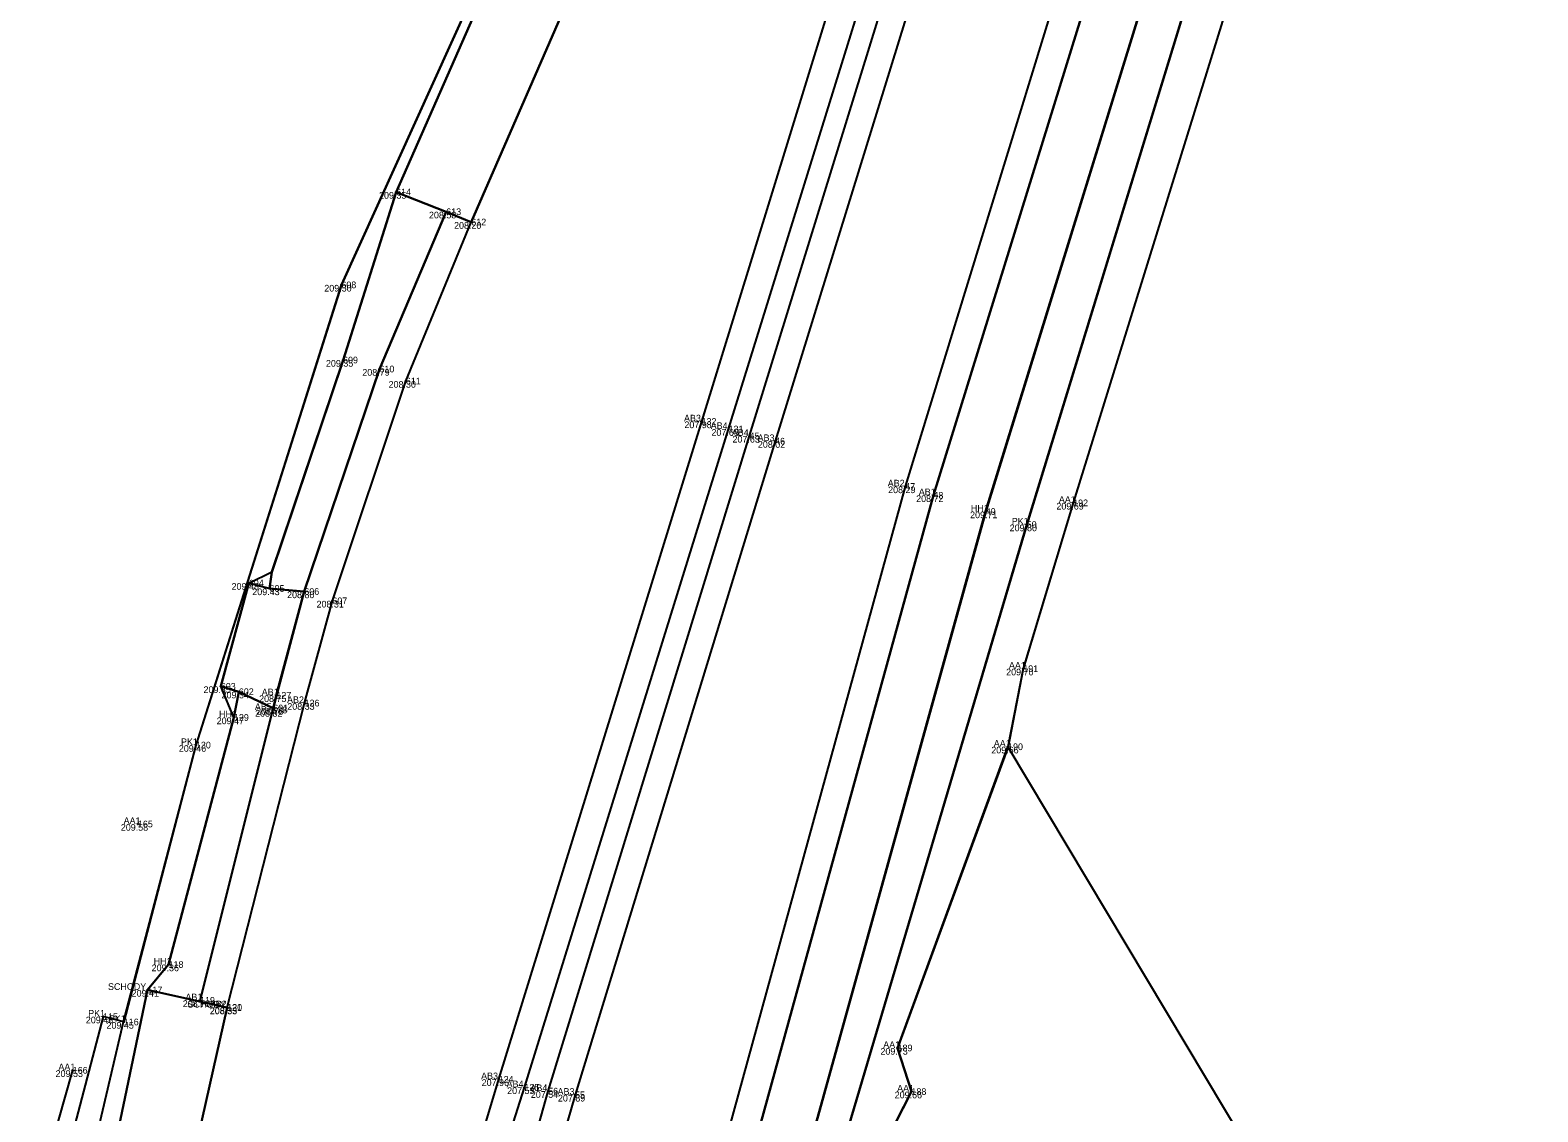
# Model space of a CAD drawing. Extents: x -262982 to -262706, y -1238714 to -1237093.
# Drawn here: x -262956 to -262910.85, y -1238361.66 to -1238329.27 of the extents above; entities that cross this region are included whole.
import ezdxf

# ---------------------------------------------------------------- set-up
doc = ezdxf.new("R2010")
doc.units = 0
for name, color, linetype in [('01_Hrana_betónu', 7, 'Continuous'), ('02_Oplotenie', 7, 'Continuous'), ('03_Asfalt', 7, 'Continuous'), ('05_Hrana_terénu', 7, 'Continuous'), ('06_Schody', 7, 'Continuous'), ('07_Iné', 7, 'Continuous'), ('Groma (21)', 7, 'Continuous'), ('Groma (22)', 7, 'Continuous'), ('Groma (23)', 7, 'Continuous'), ('Groma (24)', 7, 'Continuous'), ('U002_Asfalt', 7, 'Continuous'), ('U002_Betónové panely', 7, 'Continuous'), ('U002_Betóny_prídavné', 7, 'Continuous'), ('U002_Schody', 7, 'Continuous'), ('U002_Zeleň_mimo', 7, 'Continuous'), ('U002_Zeleň_vnútro', 7, 'Continuous'), ('U002_Zeleň_zatrávňovač', 7, 'Continuous')]:
    doc.layers.add(name, color=color, linetype=linetype)

msp = doc.modelspace()

# ---------------------------------------------------------------- linework, layer by layer
at = {"layer": '01_Hrana_betónu'}
for points in [[(-262944.213, -1238387.387), (-262944.634, -1238381.789), (-262944.5, -1238371.343), (-262941.2, -1238360.927), (-262935.086, -1238341.218), (-262927.632, -1238317.179), (-262920.793, -1238295.265), (-262911.171, -1238262.813), (-262915.352, -1238261.064), (-262915.337, -1238259.329), (-262909.866, -1238261.629), (-262904.904, -1238263.716)], [(-262916.095, -1238261.519), (-262911.974, -1238263.293), (-262921.591, -1238294.909), (-262928.534, -1238317.073), (-262935.896, -1238340.99), (-262941.971, -1238360.685), (-262945.096, -1238371.115), (-262945.34, -1238381.803), (-262945.412, -1238387.557)], [(-262941.714, -1238387.032), (-262942.991, -1238380.859), (-262943.934, -1238373.35), (-262940.485, -1238361.041), (-262934.456, -1238341.421), (-262927.277, -1238318.134), (-262920.116, -1238294.802), (-262913.64, -1238273.614), (-262910.214, -1238263.245), (-262905.769, -1238265.099), (-262904.904, -1238263.716)], [(-262905.769, -1238265.099), (-262909.81, -1238264.181), (-262912.956, -1238273.861), (-262919.396, -1238295.066), (-262926.538, -1238318.409), (-262933.693, -1238341.579), (-262939.683, -1238361.151), (-262943.246, -1238373.477), (-262942.259, -1238380.752), (-262940.526, -1238386.713)], [(-262905.769, -1238265.099), (-262909.014, -1238275.12), (-262915.393, -1238296.189), (-262922.597, -1238319.497), (-262929.796, -1238342.936), (-262935.083, -1238362.17), (-262937.995, -1238374.567), (-262938.788, -1238380.26), (-262939.46, -1238386.668), (-262940.526, -1238386.713), (-262940.498, -1238386.859)], [(-262940.36, -1238387.407), (-262939.388, -1238387.391), (-262938.822, -1238386.902), (-262937.88, -1238380.385), (-262937.119, -1238374.802), (-262934.23, -1238362.39), (-262928.952, -1238343.2), (-262921.717, -1238319.813), (-262915.107, -1238298.192), (-262908.208, -1238275.423), (-262904.855, -1238265.436)], [(-262950.921, -1238358.358), (-262948.72, -1238349.57), (-262948.626, -1238349.19), (-262947.79, -1238346.08), (-262945.54, -1238339.42), (-262943.54, -1238334.71)], [(-262950.104, -1238358.539), (-262947.782, -1238349.422), (-262946.95, -1238346.36), (-262944.75, -1238339.78), (-262942.79, -1238335.02)]]:
    msp.add_lwpolyline(points, dxfattribs=at)
at = {"layer": '02_Oplotenie'}
msp.add_lwpolyline([(-262939.39, -1238320.83), (-262941.19, -1238324.79), (-262946.68, -1238336.9), (-262951.035, -1238350.68), (-262953.195, -1238358.97), (-262953.815, -1238358.809), (-262955.312, -1238364.513), (-262954.553, -1238364.724), (-262954.681, -1238366.785), (-262954.024, -1238372.698), (-262953.142, -1238376.2), (-262951.104, -1238384.342), (-262949.016, -1238390.045), (-262944.443, -1238389.969), (-262936.906, -1238389.616), (-262935.581, -1238380.82), (-262934.566, -1238375.513), (-262931.812, -1238363.194), (-262926.159, -1238344.076), (-262918.903, -1238320.384), (-262912.242, -1238298.942), (-262905.326, -1238276.054), (-262902.598, -1238266.292), (-262902.107, -1238264.892)], dxfattribs=at)
at = {"layer": '03_Asfalt'}
for points in [[(-262917.941, -1238321.4), (-262924.768, -1238343.427), (-262926.262, -1238348.392), (-262926.717, -1238350.729), (-262930.026, -1238359.749), (-262929.61, -1238361.054), (-262931.199, -1238364.162)], [(-262955.999, -1238364.917), (-262954.725, -1238360.416)]]:
    msp.add_lwpolyline(points, dxfattribs=at)
at = {"layer": '05_Hrana_terénu'}
msp.add_lwpolyline([(-262920.126, -1238320.151), (-262927.385, -1238343.686), (-262932.704, -1238362.854), (-262935.453, -1238375.219), (-262936.279, -1238380.57), (-262937.519, -1238387.253), (-262938.314, -1238388.733), (-262939.759, -1238389.403), (-262945.681, -1238389.45), (-262947.587, -1238388.865), (-262949.049, -1238387.288), (-262950.436, -1238384.21), (-262953.347, -1238372.702), (-262953.777, -1238366.63), (-262954.163, -1238366.041), (-262952.487, -1238358.01), (-262951.855, -1238357.25), (-262949.897, -1238349.853), (-262950.29, -1238348.92), (-262949.45, -1238345.83), (-262948.76, -1238345.496), (-262946.63, -1238339.15), (-262945.04, -1238334.12), (-262941.75, -1238326.63)], dxfattribs=at)
at = {"layer": '06_Schody'}
for points in [[(-262942.79, -1238335.02), (-262943.54, -1238334.71), (-262945.04, -1238334.12), (-262941.75, -1238326.63), (-262940.4, -1238327.16), (-262939.53, -1238327.53)], [(-262951.91, -1238366.581), (-262952.759, -1238366.382), (-262954.163, -1238366.041), (-262952.487, -1238358.01), (-262950.921, -1238358.358), (-262950.104, -1238358.539)]]:
    msp.add_lwpolyline(points, close=True, dxfattribs=at)
at = {"layer": '07_Iné'}
msp.add_lwpolyline([(-262948.72, -1238349.57), (-262949.75, -1238349.08), (-262950.29, -1238348.92), (-262949.45, -1238345.83), (-262948.83, -1238345.99), (-262947.79, -1238346.08)], dxfattribs=at)
at = {"layer": 'Groma (21)'}
for centre in [(-262945.04, -1238334.12), (-262943.54, -1238334.71), (-262942.79, -1238335.02), (-262946.68, -1238336.9), (-262946.63, -1238339.15), (-262945.54, -1238339.42), (-262944.75, -1238339.78), (-262935.896, -1238340.99), (-262935.086, -1238341.218), (-262934.456, -1238341.421), (-262933.693, -1238341.579), (-262929.796, -1238342.936), (-262928.952, -1238343.2), (-262924.768, -1238343.427), (-262927.385, -1238343.686), (-262926.159, -1238344.076), (-262949.45, -1238345.83), (-262948.83, -1238345.99), (-262947.79, -1238346.08), (-262946.95, -1238346.36), (-262926.262, -1238348.392), (-262950.29, -1238348.92), (-262949.75, -1238349.08), (-262948.626, -1238349.19), (-262948.747, -1238349.629), (-262948.72, -1238349.57), (-262947.782, -1238349.422), (-262949.897, -1238349.853), (-262951.035, -1238350.68), (-262926.717, -1238350.729), (-262952.772, -1238353.044), (-262951.855, -1238357.25), (-262952.487, -1238358.01), (-262950.912, -1238358.322), (-262953.815, -1238358.809), (-262950.104, -1238358.539), (-262950.099, -1238358.531), (-262953.195, -1238358.97), (-262930.026, -1238359.749), (-262954.725, -1238360.416), (-262941.971, -1238360.685), (-262941.2, -1238360.927), (-262940.485, -1238361.041), (-262929.61, -1238361.054), (-262939.683, -1238361.151)]:
    msp.add_circle(centre, 0.01, dxfattribs=at)
at = {"layer": 'U002_Asfalt'}
msp.add_lwpolyline([(-262931.2, -1238364.16), (-262929.61, -1238361.05), (-262930.03, -1238359.75), (-262926.72, -1238350.73), (-262915.49, -1238369.52)], dxfattribs=at)
at = {"layer": 'U002_Betónové panely'}
for points in [[(-262921.72, -1238319.81), (-262928.95, -1238343.2), (-262934.23, -1238362.39)], [(-262951.91, -1238366.58), (-262950.1, -1238358.54), (-262950.92, -1238358.36), (-262948.72, -1238349.57), (-262948.63, -1238349.19), (-262947.79, -1238346.08), (-262945.54, -1238339.42), (-262943.54, -1238334.71), (-262942.79, -1238335.02), (-262939.53, -1238327.53)]]:
    msp.add_lwpolyline(points, dxfattribs=at)
at = {"layer": 'U002_Betóny_prídavné'}
msp.add_lwpolyline([(-262948.72, -1238349.57), (-262949.75, -1238349.08), (-262950.29, -1238348.92), (-262949.45, -1238345.83), (-262948.83, -1238345.99), (-262947.79, -1238346.08)], close=True, dxfattribs=at)
at = {"layer": 'U002_Schody'}
for points in [[(-262943.54, -1238334.71), (-262945.04, -1238334.12), (-262941.75, -1238326.63), (-262940.4, -1238327.16), (-262939.53, -1238327.53), (-262942.79, -1238335.02)], [(-262950.1, -1238358.54), (-262951.91, -1238366.58), (-262952.76, -1238366.38), (-262954.16, -1238366.04), (-262952.49, -1238358.01), (-262950.92, -1238358.36)]]:
    msp.add_lwpolyline(points, close=True, dxfattribs=at)
at = {"layer": 'U002_Zeleň_mimo'}
for points in [[(-262931.81, -1238363.19), (-262926.16, -1238344.08), (-262918.9, -1238320.38)], [(-262917.94, -1238321.4), (-262924.77, -1238343.43), (-262926.26, -1238348.39), (-262926.72, -1238350.73), (-262930.03, -1238359.75), (-262929.61, -1238361.05), (-262931.2, -1238364.16)]]:
    msp.add_lwpolyline(points, dxfattribs=at)
at = {"layer": 'U002_Zeleň_vnútro'}
for points in [[(-262918.9, -1238320.38), (-262926.16, -1238344.08), (-262931.81, -1238363.19), (-262934.57, -1238375.51), (-262935.58, -1238380.82), (-262936.91, -1238389.62), (-262944.44, -1238389.97), (-262949.02, -1238390.05), (-262951.1, -1238384.34), (-262954.02, -1238372.7), (-262954.68, -1238366.78), (-262954.55, -1238364.72), (-262953.2, -1238358.97), (-262951.03, -1238350.68), (-262946.68, -1238336.9), (-262941.19, -1238324.79)], [(-262932.7, -1238362.85), (-262927.39, -1238343.69), (-262920.13, -1238320.15)], [(-262941.75, -1238326.63), (-262945.04, -1238334.12), (-262946.63, -1238339.15), (-262948.76, -1238345.5), (-262948.83, -1238345.99), (-262949.45, -1238345.83), (-262950.29, -1238348.92), (-262949.75, -1238349.08), (-262949.9, -1238349.85), (-262951.86, -1238357.25), (-262952.49, -1238358.01), (-262954.16, -1238366.04)]]:
    msp.add_lwpolyline(points, dxfattribs=at)
at = {"layer": 'U002_Zeleň_zatrávňovač'}
for points in [[(-262934.23, -1238362.39), (-262928.95, -1238343.2), (-262921.72, -1238319.81)], [(-262920.13, -1238320.15), (-262927.39, -1238343.69), (-262932.7, -1238362.85)]]:
    msp.add_lwpolyline(points, dxfattribs=at)
for points in [[(-262946.63, -1238339.15), (-262945.04, -1238334.12), (-262943.54, -1238334.71), (-262945.54, -1238339.42), (-262947.79, -1238346.08), (-262948.83, -1238345.99), (-262948.76, -1238345.5)], [(-262949.75, -1238349.08), (-262948.72, -1238349.57), (-262950.92, -1238358.36), (-262952.49, -1238358.01), (-262951.86, -1238357.25), (-262949.9, -1238349.85)]]:
    msp.add_lwpolyline(points, close=True, dxfattribs=at)

# ---------------------------------------------------------------- texts
at = {"layer": 'Groma (22)'}
for s, p in [('614', (-262945.04, -1238334.22)), ('613', (-262943.54, -1238334.81)), ('612', (-262942.79, -1238335.12)), ('608', (-262946.68, -1238337)), ('609', (-262946.63, -1238339.25)), ('610', (-262945.54, -1238339.52)), ('611', (-262944.75, -1238339.88)), ('132', (-262935.896, -1238341.09)), ('131', (-262935.086, -1238341.318)), ('45', (-262934.456, -1238341.521)), ('46', (-262933.693, -1238341.679)), ('47', (-262929.796, -1238343.036)), ('48', (-262928.952, -1238343.3)), ('192', (-262924.768, -1238343.527)), ('49', (-262927.385, -1238343.786)), ('50', (-262926.159, -1238344.176)), ('604', (-262949.45, -1238345.93)), ('605', (-262948.83, -1238346.09)), ('606', (-262947.79, -1238346.18)), ('607', (-262946.95, -1238346.46)), ('191', (-262926.262, -1238348.492)), ('603', (-262950.29, -1238349.02)), ('602', (-262949.75, -1238349.18)), ('127', (-262948.626, -1238349.29)), ('126', (-262947.782, -1238349.522)), ('129', (-262949.897, -1238349.953)), ('128', (-262948.747, -1238349.729)), ('601', (-262948.72, -1238349.67)), ('130', (-262951.035, -1238350.78)), ('190', (-262926.717, -1238350.829)), ('165', (-262952.772, -1238353.144)), ('118', (-262951.855, -1238357.35)), ('117', (-262952.487, -1238358.11)), ('119', (-262950.912, -1238358.422)), ('115', (-262953.815, -1238358.909)), ('121', (-262950.104, -1238358.639)), ('120', (-262950.099, -1238358.631)), ('116', (-262953.195, -1238359.07)), ('189', (-262930.026, -1238359.849)), ('166', (-262954.725, -1238360.516)), ('124', (-262941.971, -1238360.785)), ('125', (-262941.2, -1238361.027)), ('56', (-262940.485, -1238361.141)), ('55', (-262939.683, -1238361.251)), ('188', (-262929.61, -1238361.154))]:
    msp.add_text(s, height=0.2, dxfattribs=at).set_placement(p)
at = {"layer": 'Groma (23)'}
for s, p in [('209.35', (-262945.552, -1238334.32)), ('208.58', (-262944.057, -1238334.91)), ('208.20', (-262943.306, -1238335.22)), ('209.50', (-262947.191, -1238337.1)), ('209.35', (-262947.142, -1238339.35)), ('208.79', (-262946.053, -1238339.62)), ('208.30', (-262945.266, -1238339.98)), ('207.98', (-262936.409, -1238341.19)), ('207.65', (-262935.599, -1238341.418)), ('207.63', (-262934.969, -1238341.621)), ('208.02', (-262934.209, -1238341.779)), ('208.29', (-262930.308, -1238343.136)), ('208.72', (-262929.469, -1238343.4)), ('209.69', (-262925.27, -1238343.627)), ('209.71', (-262927.854, -1238343.886)), ('209.80', (-262926.67, -1238344.276)), ('209.48', (-262949.967, -1238346.03)), ('209.43', (-262949.347, -1238346.19)), ('208.80', (-262948.306, -1238346.28)), ('208.31', (-262947.423, -1238346.56)), ('209.70', (-262926.774, -1238348.592)), ('209.45', (-262950.807, -1238349.12)), ('209.34', (-262950.267, -1238349.28)), ('208.75', (-262949.143, -1238349.39)), ('208.82', (-262949.264, -1238349.829)), ('208.76', (-262949.233, -1238349.77)), ('208.33', (-262948.299, -1238349.622)), ('209.47', (-262950.414, -1238350.053)), ('209.46', (-262951.547, -1238350.88)), ('209.66', (-262927.219, -1238350.929)), ('209.58', (-262953.284, -1238353.244)), ('209.36', (-262952.362, -1238357.45)), ('209.41', (-262952.96, -1238358.21)), ('208.70', (-262951.429, -1238358.522)), ('209.48', (-262954.332, -1238359.009)), ('208.33', (-262950.621, -1238358.739)), ('208.33', (-262950.616, -1238358.731)), ('209.45', (-262953.712, -1238359.17)), ('209.73', (-262930.539, -1238359.949)), ('209.53', (-262955.237, -1238360.616)), ('207.96', (-262942.479, -1238360.885)), ('207.53', (-262941.717, -1238361.127)), ('207.54', (-262941.007, -1238361.241)), ('209.66', (-262930.112, -1238361.254)), ('207.89', (-262940.196, -1238361.351))]:
    msp.add_text(s, height=0.2, dxfattribs=at).set_placement(p)
at = {"layer": 'Groma (24)'}
for s, p in [('AB3', (-262936.42, -1238340.99)), ('AB4', (-262935.62, -1238341.218)), ('AB4', (-262934.99, -1238341.421)), ('AB3', (-262934.217, -1238341.579)), ('AB2', (-262930.32, -1238342.936)), ('AB1', (-262929.39, -1238343.2)), ('AA1', (-262925.196, -1238343.427)), ('HH1', (-262927.832, -1238343.686)), ('PK1', (-262926.606, -1238344.076)), ('AA1', (-262926.69, -1238348.392)), ('AB1', (-262949.064, -1238349.19)), ('AB2', (-262948.306, -1238349.422)), ('HH1', (-262950.344, -1238349.853)), ('AB5', (-262949.271, -1238349.629)), ('PK1', (-262951.482, -1238350.68)), ('AA1', (-262927.145, -1238350.729)), ('AA1', (-262953.2, -1238353.044)), ('HH1', (-262952.302, -1238357.25)), ('SCHODY', (-262953.668, -1238358.01)), ('AB1', (-262951.35, -1238358.322)), ('SCHODY', (-262951.285, -1238358.539)), ('AB2', (-262950.623, -1238358.531)), ('PK1', (-262954.262, -1238358.809)), ('PK1', (-262953.642, -1238358.97)), ('AA1', (-262930.454, -1238359.749)), ('AA1', (-262955.153, -1238360.416)), ('AB3', (-262942.495, -1238360.685)), ('AB4', (-262941.734, -1238360.927)), ('AB4', (-262941.019, -1238361.041)), ('AB3', (-262940.207, -1238361.151)), ('AA1', (-262930.038, -1238361.054))]:
    msp.add_text(s, height=0.2, dxfattribs=at).set_placement(p)

doc.saveas('drawing.dxf')
